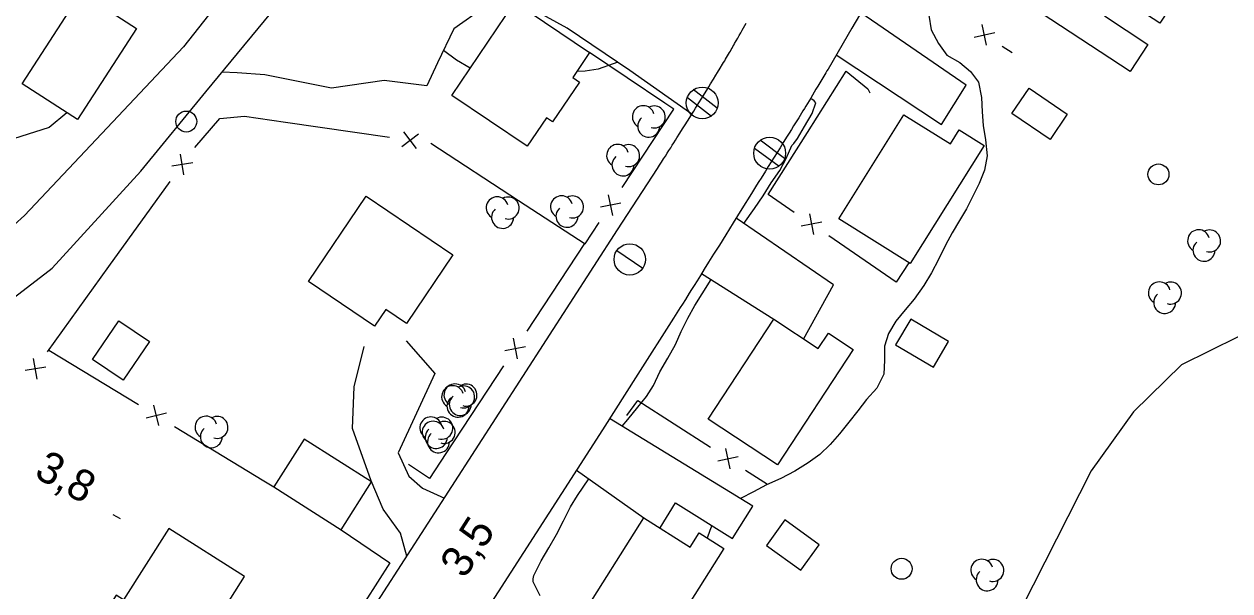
# Model space of a CAD drawing. Extents: x 219136 to 222520, y 5421589 to 5424530.
# Drawn here: x 221316.4 to 221431.4, y 5422722 to 5422776 of the extents above; entities that cross this region are included whole.
import ezdxf

# ---------------------------------------------------------------- set-up
doc = ezdxf.new("R2010")
doc.units = 0
for name, color, linetype in [('Level 19', 7, 'Continuous'), ('Level 2', 7, 'Continuous'), ('Level 21', 7, 'Continuous'), ('Level 22', 7, 'Continuous'), ('Level 3', 7, 'Continuous'), ('Level 31', 7, 'Continuous'), ('Level 36', 7, 'Continuous'), ('Level 37', 7, 'Continuous'), ('Level 44', 7, 'Continuous')]:
    doc.layers.add(name, color=color, linetype=linetype)

msp = doc.modelspace()

# ---------------------------------------------------------------- linework, layer by layer
at = {"layer": 'Level 19'}
for points in [[(221380.05, 5422767.44), (221374.14, 5422771.61), (221368.14, 5422775.65), (221363.21, 5422778.37), (221360.23, 5422777.6), (221357.34, 5422775.59), (221355.79, 5422772.35), (221354.78, 5422770.15), (221350.69, 5422770.64), (221345.68, 5422769.93), (221339.32, 5422771.19), (221336.66, 5422771.4), (221335.24, 5422771.46)], [(221393.83, 5422773.11), (221403.87, 5422766.47), (221406.23, 5422770.22), (221396.18, 5422777.12), (221396.18, 5422777.12)], [(221390.71, 5422746), (221393.57, 5422751.16), (221384.26, 5422757.51)], [(221380.97, 5422752.24), (221387.86, 5422747.88)], [(221352.81, 5422745.82), (221355.53, 5422742.72), (221352.03, 5422735.15), (221353.05, 5422732.91), (221354.35, 5422731.77), (221356.44, 5422730.83)], [(221352.86, 5422725.28), (221352.27, 5422727.49), (221350.6, 5422729.77), (221349.47, 5422732.47), (221347.67, 5422737.46), (221347.82, 5422741.45), (221348.79, 5422745.27)], [(221377.02, 5422727.98), (221378.48, 5422730.37), (221383.92, 5422726.97), (221385.87, 5422730.06), (221372.2, 5422738.43)], [(221369.03, 5422733.49), (221375.48, 5422728.95)]]:
    msp.add_lwpolyline(points, dxfattribs=at)
at = {"layer": 'Level 2'}
for points in [[(221402.67, 5422776.87), (221402.89, 5422775.48), (221403.58, 5422774.19), (221404.37, 5422773.06), (221405.62, 5422772.36), (221406.62, 5422771.51), (221407.38, 5422770.48), (221407.69, 5422769.03), (221407.75, 5422767.68), (221407.83, 5422766.36), (221408.06, 5422765.01), (221408.22, 5422763.47), (221407.98, 5422762.1), (221407.47, 5422760.84), (221406.86, 5422759.61), (221406.24, 5422758.43), (221405.59, 5422757.31), (221404.88, 5422756.11), (221404.26, 5422754.96), (221403.58, 5422753.59), (221402.9, 5422752.31), (221402.19, 5422751.1), (221401.27, 5422749.8), (221400.4, 5422748.77), (221399.5, 5422747.7), (221398.81, 5422746.52), (221398.43, 5422745.31), (221398.42, 5422743.98), (221398.36, 5422742.64), (221397.69, 5422741.31), (221396.72, 5422740.23), (221395.87, 5422739.16), (221395.03, 5422738.08), (221394.12, 5422736.97), (221393.24, 5422735.93), (221392.25, 5422735), (221391.14, 5422734.2)], [(221358.91, 5422771.82), (221357.6, 5422772.58), (221356.35, 5422773.52)], [(221372.99, 5422772.39), (221372.54, 5422772.23), (221371.12, 5422771.74), (221369.86, 5422771.53), (221369.09, 5422771.52)], [(221385.01, 5422757), (221386.03, 5422758.45), (221386.84, 5422759.65), (221387.63, 5422760.9), (221388.45, 5422762.07), (221389.04, 5422763.2), (221389.59, 5422764.46), (221389.77, 5422764.64), (221390.14, 5422765.11), (221390.8, 5422766.28), (221391.53, 5422767.5), (221391.89, 5422768.53), (221391.72, 5422768.72), (221391.48, 5422768.86), (221391.36, 5422768.92)], [(221373.4, 5422737.69), (221373.94, 5422738.33), (221374.89, 5422739.51), (221375.72, 5422740.52), (221376.4, 5422741.58), (221376.98, 5422742.88), (221377.75, 5422744.18), (221378.48, 5422745.47), (221379.02, 5422746.73), (221379.67, 5422748), (221380.33, 5422749.19), (221381.04, 5422750.31), (221381.89, 5422751.66)], [(221391.14, 5422734.2), (221389.86, 5422733.4), (221388.55, 5422732.71), (221387.18, 5422732.1), (221385.94, 5422731.44), (221384.7, 5422730.78)], [(221365.57, 5422721.51), (221364.9, 5422722.83), (221364.9, 5422723.13), (221364.97, 5422723.44), (221365.68, 5422724.84), (221366.42, 5422726.09), (221367.15, 5422727.36), (221367.81, 5422728.67), (221368.46, 5422730.01), (221369.13, 5422731.09), (221370.21, 5422732.66)], [(221381.96, 5422728.2), (221381.76, 5422727.73), (221381.5, 5422727.02)]]:
    msp.add_lwpolyline(points, dxfattribs=at)
at = {"layer": 'Level 21'}
for points in [[(221383.81, 5422856.65), (221376.31, 5422845.19), (221367.09, 5422830.11), (221355.85, 5422811.59), (221345.1, 5422793.68), (221337.42, 5422781.3), (221331.57, 5422773.87), (221324.26, 5422766.14), (221316.39, 5422757.78), (221307.49, 5422749.76)], [(221310.99, 5422746.58), (221319.03, 5422752.77), (221327.48, 5422762), (221333.69, 5422769.57), (221341.7, 5422779.31), (221346.63, 5422786.61), (221352.5, 5422795.29), (221358.52, 5422804.94), (221365.09, 5422815.49), (221371.28, 5422825.96), (221377.09, 5422835.4), (221381.93, 5422843.03), (221386.2, 5422849.85), (221388.61, 5422853.38), (221388.61, 5422853.38)], [(221397.61, 5422779.56), (221395.32, 5422775.66), (221393.04, 5422771.75), (221392.94, 5422771.57), (221392.84, 5422771.4), (221392.74, 5422771.23), (221392.64, 5422771.07), (221392.44, 5422770.74), (221392.25, 5422770.42), (221392.07, 5422770.11), (221391.89, 5422769.82), (221391.72, 5422769.53), (221391.55, 5422769.25), (221391.39, 5422768.98), (221391.23, 5422768.72), (221391.07, 5422768.47), (221390.93, 5422768.22), (221390.78, 5422767.99), (221390.64, 5422767.76), (221390.5, 5422767.53), (221390.24, 5422767.1), (221389.99, 5422766.7), (221389.76, 5422766.32), (221389.54, 5422765.97), (221389.33, 5422765.64), (221389.14, 5422765.33), (221388.77, 5422764.75), (221388.46, 5422764.24), (221387.34, 5422762.46), (221387.06, 5422762.02), (221386.65, 5422761.35), (221386.44, 5422761.01), (221386.23, 5422760.68), (221385.74, 5422759.89), (221384.81, 5422758.4), (221384, 5422757.09), (221383.29, 5422755.95), (221382.67, 5422754.95), (221382.12, 5422754.08), (221381.65, 5422753.32), (221381.23, 5422752.65), (221380.86, 5422752.07), (221380.54, 5422751.56), (221380.26, 5422751.11), (221380.02, 5422750.72), (221379.8, 5422750.38), (221379.43, 5422749.78), (221379.14, 5422749.33), (221378.93, 5422749), (221378.61, 5422748.49), (221378.29, 5422747.99), (221374.9, 5422742.66), (221371.51, 5422737.34)], [(221372.96, 5422756.41), (221374.86, 5422759.34), (221376.76, 5422762.27), (221376.96, 5422762.58), (221377.15, 5422762.88), (221377.34, 5422763.17), (221377.52, 5422763.45), (221377.69, 5422763.72), (221377.86, 5422763.98), (221378.03, 5422764.24), (221378.18, 5422764.48), (221378.34, 5422764.72), (221378.48, 5422764.96), (221378.63, 5422765.18), (221378.9, 5422765.62), (221379.16, 5422766.03), (221379.4, 5422766.41), (221379.63, 5422766.77), (221379.84, 5422767.11), (221380.04, 5422767.43), (221380.23, 5422767.73), (221380.4, 5422768.01), (221380.56, 5422768.27), (221380.72, 5422768.52), (221381, 5422768.98), (221381.25, 5422769.38), (221381.47, 5422769.74), (221381.66, 5422770.05), (221381.82, 5422770.32), (221382.11, 5422770.79), (221382.33, 5422771.15), (221382.49, 5422771.42), (221382.74, 5422771.82), (221382.98, 5422772.22), (221383.08, 5422772.38), (221383.18, 5422772.54), (221383.27, 5422772.7), (221383.36, 5422772.86), (221383.45, 5422773.01), (221383.54, 5422773.17), (221383.63, 5422773.32), (221383.72, 5422773.46), (221383.8, 5422773.61), (221383.88, 5422773.75), (221383.97, 5422773.89), (221384.05, 5422774.03), (221384.12, 5422774.17), (221384.28, 5422774.44), (221384.43, 5422774.7), (221384.57, 5422774.96), (221384.71, 5422775.2), (221384.84, 5422775.44), (221384.97, 5422775.67), (221385.1, 5422775.9), (221385.22, 5422776.12)], [(221304.55, 5422650.11), (221323.53, 5422679.64), (221341.35, 5422707.46), (221372.96, 5422756.41)], [(221371.51, 5422737.34), (221350.12, 5422704.12), (221329.57, 5422671.81), (221326.2, 5422666.52), (221306.01, 5422635.14)]]:
    msp.add_lwpolyline(points, dxfattribs=at)
at = {"layer": 'Level 22'}
msp.add_lwpolyline([(221454.3, 5422810.51), (221459.28, 5422805.72), (221464.97, 5422795.86), (221467.99, 5422787.86), (221469.08, 5422780.24), (221468.76, 5422774.06), (221466.75, 5422768.18), (221462.44, 5422761.73), (221458.14, 5422757.08), (221452.23, 5422753.51), (221445.07, 5422750.57), (221438.34, 5422748.37), (221432.15, 5422746.2), (221426.76, 5422743.55), (221422.19, 5422739.04), (221418.14, 5422733.43), (221412.6, 5422722.52), (221397.76, 5422693.4), (221390.31, 5422680.23), (221384.4, 5422671.25), (221379.74, 5422663.83)], dxfattribs=at)
at = {"layer": 'Level 3'}
msp.add_line((221324.8, 5422729.25), (221325.5, 5422728.87), dxfattribs=at)
at = {"layer": 'Level 31'}
for points in [[(221421.85, 5422771.5), (221408.57, 5422780.24), (221410.3, 5422782.87), (221418.01, 5422777.8), (221419.15, 5422779.52), (221411.24, 5422784.73), (221413.08, 5422787.54), (221417.46, 5422784.66), (221418.18, 5422785.75), (221419.76, 5422784.71), (221419.1, 5422783.71), (221426.48, 5422778.86), (221424.68, 5422776.12), (221420.69, 5422778.75), (221419.42, 5422776.81), (221423.55, 5422774.09)], [(221327.08, 5422775.62), (221321.44, 5422766.92), (221316.15, 5422770.35), (221321.78, 5422779.06)], [(221357.16, 5422769.22), (221363.16, 5422778.13), (221370.3, 5422773.32), (221368.69, 5422770.93), (221369.32, 5422770.5), (221366.76, 5422766.7), (221366.17, 5422767.1), (221364.34, 5422764.38)], [(221412.21, 5422769.91), (221415.85, 5422767.43), (221414.22, 5422765.03), (221410.57, 5422767.5)], [(221407.92, 5422764.45), (221400.87, 5422753.2), (221394.06, 5422757.47), (221400.28, 5422767.39), (221404.72, 5422764.6), (221405.56, 5422765.94)], [(221348.97, 5422759.63), (221357.26, 5422754.04), (221352.84, 5422747.49), (221350.86, 5422748.82), (221349.78, 5422747.22), (221343.48, 5422751.48)], [(221328.3, 5422745.77), (221325.79, 5422742.07), (221322.88, 5422744.05), (221325.39, 5422747.74)], [(221395.45, 5422745), (221388.22, 5422734.01), (221381.6, 5422738.37), (221387.86, 5422747.88), (221392.11, 5422745.08), (221393.09, 5422746.56)], [(221399.49, 5422745.45), (221403.09, 5422743.32), (221404.54, 5422745.77), (221400.94, 5422747.9)], [(221340.18, 5422731.89), (221346.59, 5422727.81), (221349.49, 5422732.37), (221343.08, 5422736.45)], [(221383.1, 5422726.01), (221376.09, 5422714.94), (221369.32, 5422719.23), (221375.48, 5422728.95), (221379.89, 5422726.16), (221380.74, 5422727.5)], [(221387.16, 5422726.32), (221390.43, 5422723.95), (221392.19, 5422726.37), (221388.92, 5422728.74)], [(221329.7, 5422711.21), (221337.38, 5422723.35), (221330.14, 5422727.93), (221325.84, 5422721.13), (221325.12, 5422721.58), (221322.53, 5422717.44), (221323.31, 5422716.95), (221322.54, 5422715.73)]]:
    msp.add_lwpolyline(points, close=True, dxfattribs=at)
at = {"layer": 'Level 36'}
for p, q in [((221379.62, 5422769.03), (221381.92, 5422767.26)), ((221382.46, 5422768.01), (221380.16, 5422769.78)), ((221386.04, 5422764.2), (221388.37, 5422762.47)), ((221388.9, 5422763.22), (221386.57, 5422764.95)), ((221372.88, 5422754.43), (221375.36, 5422752.75))]:
    msp.add_line(p, q, dxfattribs=at)
for centre, radius in [((221381.04, 5422768.51), 1.52), ((221331.82, 5422766.74), 1), ((221387.47, 5422763.72), 1.52), ((221424.56, 5422761.7), 1), ((221374.13, 5422753.59), 1.5), ((221400.06, 5422724.09), 1)]:
    msp.add_circle(centre, radius, dxfattribs=at)
at = {"layer": 'Level 37'}
for p, q in [((221408.17, 5422774.03), (221407.74, 5422775.98)), ((221406.98, 5422774.79), (221408.94, 5422775.22)), ((221352.37, 5422764.37), (221353.97, 5422765.57)), ((221353.77, 5422764.17), (221352.57, 5422765.77)), ((221331.6, 5422761.65), (221331.28, 5422763.62)), ((221332.43, 5422762.8), (221330.45, 5422762.47)), ((221372.5, 5422757.79), (221372.1, 5422759.75)), ((221373.28, 5422758.97), (221371.32, 5422758.57)), ((221392.44, 5422757.14), (221390.47, 5422756.77)), ((221391.27, 5422757.94), (221391.64, 5422755.97)), ((221362.99, 5422746.08), (221363.39, 5422744.11)), ((221362.21, 5422744.89), (221364.17, 5422745.29)), ((221317.59, 5422742.17), (221317.26, 5422744.14)), ((221318.41, 5422743.32), (221316.44, 5422742.99)), ((221328, 5422738.47), (221329.94, 5422738.95)), ((221329.21, 5422737.74), (221328.73, 5422739.68)), ((221383.71, 5422733.61), (221383.29, 5422735.56)), ((221382.52, 5422734.37), (221384.48, 5422734.79))]:
    msp.add_line(p, q, dxfattribs=at)
for points in [[(221377.48, 5422768.5), (221370.3, 5422773.32)], [(221409.64, 5422773.93), (221410.59, 5422773.32)], [(221391.08, 5422765.7), (221394.77, 5422771.54), (221396.83, 5422769.87), (221397.04, 5422769.48)], [(221320.43, 5422767.58), (221318.74, 5422766.18), (221311.3, 5422763.82)], [(221373.4, 5422760.44), (221378.34, 5422767.92), (221377.48, 5422768.5)], [(221332.63, 5422764.25), (221335.02, 5422767.04), (221337.36, 5422767.24), (221341.29, 5422766.68)], [(221341.29, 5422766.68), (221351.19, 5422765.25)], [(221389.81, 5422758.08), (221387.34, 5422759.77), (221391.08, 5422765.7)], [(221355.15, 5422764.67), (221363.52, 5422759.21)], [(221324.43, 5422752.9), (221330.27, 5422761.01)], [(221363.52, 5422759.21), (221369.86, 5422755.07), (221371.2, 5422757.1)], [(221369.8, 5422755.11), (221369.8, 5422755.1), (221364.3, 5422746.76)], [(221400.76, 5422753.27), (221399.54, 5422751.43), (221393.11, 5422755.83)], [(221318.59, 5422744.78), (221324.43, 5422752.9)], [(221318.72, 5422744.95), (221327.26, 5422739.75)], [(221362.09, 5422743.43), (221356.58, 5422735.08)], [(221373.85, 5422738.72), (221374.91, 5422740.14), (221381.82, 5422735.67)], [(221330.68, 5422737.67), (221339.22, 5422732.47)], [(221356.58, 5422735.08), (221355.01, 5422732.7), (221353.03, 5422734.03)], [(221385.18, 5422733.5), (221387.26, 5422732.15)], [(221339.22, 5422732.47), (221340.18, 5422731.89)], [(221346.59, 5422727.81), (221351.25, 5422724.66), (221348.89, 5422720.97)]]:
    msp.add_lwpolyline(points, dxfattribs=at)
at = {"layer": 'Level 44'}
for centre, start, end in [((221375.42, 5422767.2), 15.9068, 238.5912), ((221376.47, 5422767.18), 253.0853, 118.7739), ((221375.93, 5422766.29), 131.2391, 358.6962), ((221372.97, 5422763.51), 15.9068, 238.5912), ((221374.02, 5422763.49), 253.0853, 118.7739), ((221373.48, 5422762.6), 131.2391, 358.6962), ((221361.48, 5422758.51), 15.9068, 238.5912), ((221362.53, 5422758.49), 253.0853, 118.7739), ((221367.62, 5422758.61), 15.9068, 238.5912), ((221368.67, 5422758.59), 253.0853, 118.7739), ((221361.99, 5422757.6), 131.2391, 358.6962), ((221368.13, 5422757.7), 131.2391, 358.6962), ((221428.39, 5422755.37), 15.9068, 238.5912), ((221429.44, 5422755.35), 253.0853, 118.7739), ((221428.9, 5422754.46), 131.2391, 358.6962), ((221424.65, 5422750.4), 15.9068, 238.5912), ((221425.7, 5422750.38), 253.0853, 118.7739), ((221425.16, 5422749.49), 131.2391, 358.6962), ((221357.23, 5422740.5), 15.9068, 238.5912), ((221357.45, 5422740.67), 15.9068, 238.5912), ((221358.28, 5422740.48), 253.0853, 118.7739), ((221358.5, 5422740.65), 253.0853, 118.7739), ((221357.74, 5422739.59), 131.2391, 358.6962), ((221357.96, 5422739.76), 131.2391, 358.6962), ((221333.7, 5422737.59), 15.9068, 238.5912), ((221334.75, 5422737.57), 253.0853, 118.7739), ((221355.15, 5422737.52), 15.9068, 238.5912), ((221355.37, 5422737.11), 15.9068, 238.5912), ((221356.2, 5422737.5), 253.0853, 118.7739), ((221356.42, 5422737.09), 253.0853, 118.7739), ((221334.21, 5422736.68), 131.2391, 358.6962), ((221355.66, 5422736.61), 131.2391, 358.6962), ((221355.88, 5422736.2), 131.2391, 358.6962), ((221407.71, 5422723.95), 15.9068, 238.5912), ((221408.76, 5422723.93), 253.0853, 118.7739), ((221408.22, 5422723.04), 131.2391, 358.6962)]:
    msp.add_arc(centre, 1.05, start, end, dxfattribs=at)

# ---------------------------------------------------------------- texts
at = {"layer": 'Level 3'}
for s, rotation, p in [('3,8', 331.383, (221317.19, 5422732.9)), ('3,5', 57.3363, (221358.37, 5422723.05))]:
    msp.add_text(s, height=3, rotation=rotation, dxfattribs=at).set_placement(p)

doc.saveas('drawing.dxf')
